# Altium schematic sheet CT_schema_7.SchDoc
size 278 x 170 mm
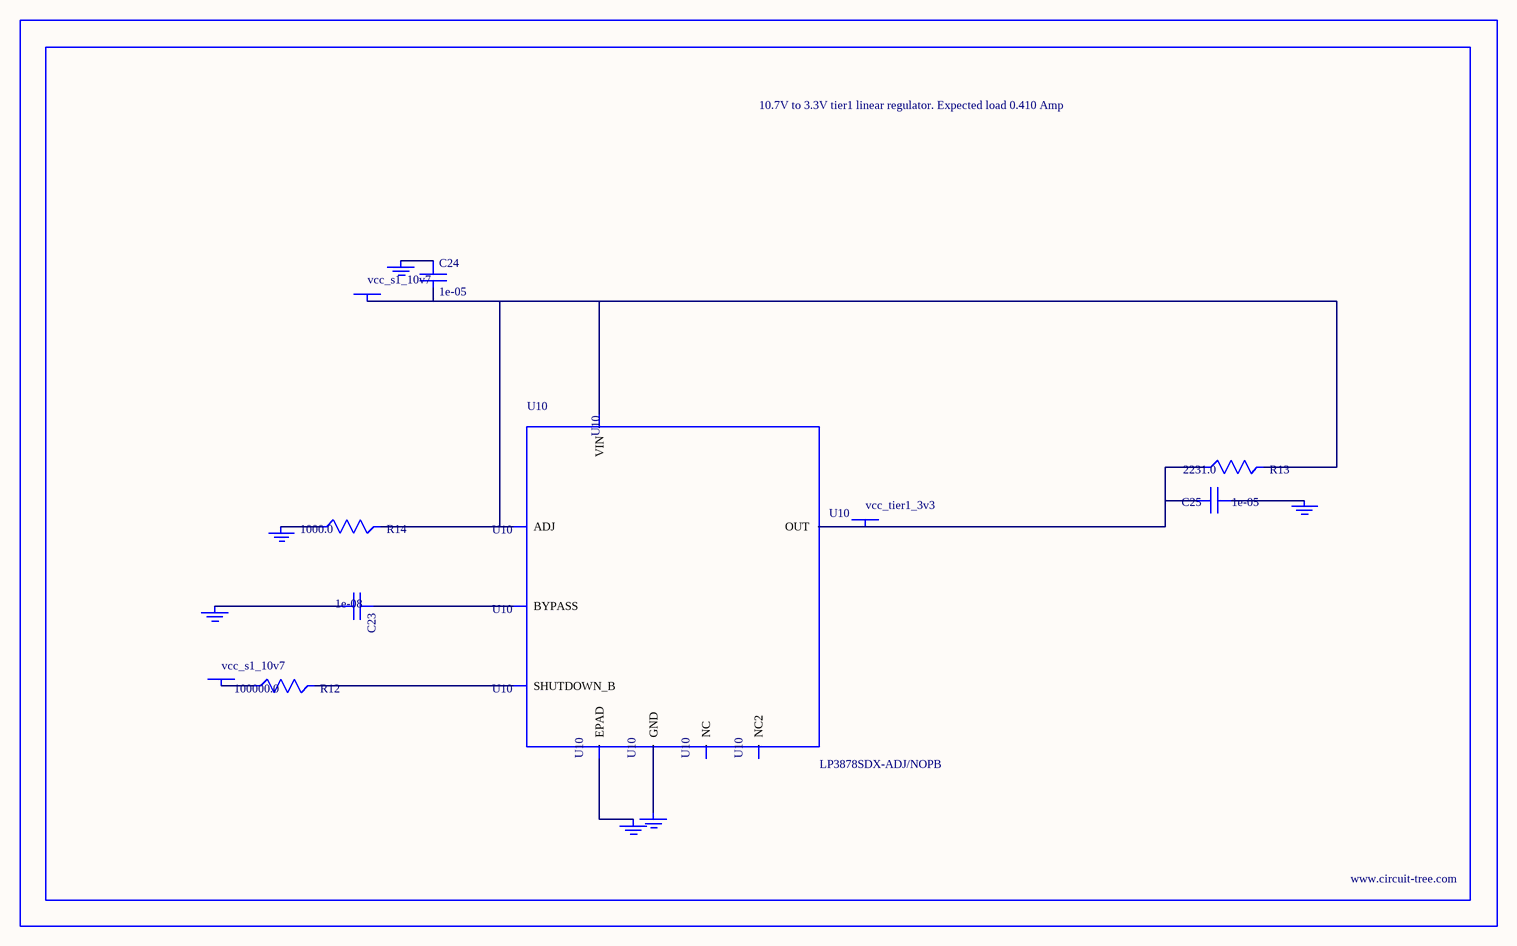
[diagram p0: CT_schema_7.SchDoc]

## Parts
BORDER6  (no value)
C23  1e-08  [C0402]
C24  1e-05  [C1206]
C25  1e-05  [C1210]
GND_INSTANCE_6_0  (no value)
GND_INSTANCE_6_1  (no value)
GND_INSTANCE_6_2  (no value)
GND_INSTANCE_6_3  (no value)
GND_INSTANCE_6_4  (no value)
GND_INSTANCE_6_5  (no value)
POWER_INSTANCE_6_0  vcc_s1_10v7
POWER_INSTANCE_6_1  vcc_s1_10v7
POWER_INSTANCE_6_2  vcc_tier1_3v3
R12  100000.0  [R0603]
R13  2231.0  [R0603]
R14  1000.0  [R0603]
U10  LP3878SDX-ADJ/NOPB  [WSON-8]

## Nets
NetC23_1: C23.1 U10.1(BYPASS)
NetC23_2: C23.2 GND_INSTANCE_6_0.0(GND)
NetC24_1: C24.1 GND_INSTANCE_6_1.0(GND)
NetC24_2: C24.2 POWER_INSTANCE_6_0.0(PWR) R13.2 R14.2 U10.4(VIN) U10.6(ADJ)
NetC25_1: C25.1 GND_INSTANCE_6_2.0(GND)
NetC25_2: C25.2 POWER_INSTANCE_6_2.0(PWR) R13.1 U10.5(OUT)
NetGND_INSTANCE_6_3_0: GND_INSTANCE_6_3.0(GND) R14.1
NetGND_INSTANCE_6_4_0: GND_INSTANCE_6_4.0(GND) U10.PAD(EPAD)
NetGND_INSTANCE_6_5_0: GND_INSTANCE_6_5.0(GND) U10.3(GND)
NetPOWER_INSTANCE_6_1_0: POWER_INSTANCE_6_1.0(PWR) R12.1
NetR12_2: R12.2 U10.8(SHUTDOWN_B)

Not connected (* = marked no-connect by the designer): U10 2(NC) 7(NC2)

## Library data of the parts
BORDER6 = BORDER_PAGE6
C23 = C0402C103K3RAC
C24 = C1206C106K3RACTU
C25 = GRM32DR61E106MA12L
GND_INSTANCE_6_0-GND_INSTANCE_6_5 = GND
POWER_INSTANCE_6_0-POWER_INSTANCE_6_2 = PWR
R12 = RC0603JR-07100KL
R13 = R13
R14 = RC0603JR-071KL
